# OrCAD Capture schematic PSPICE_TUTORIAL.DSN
size A
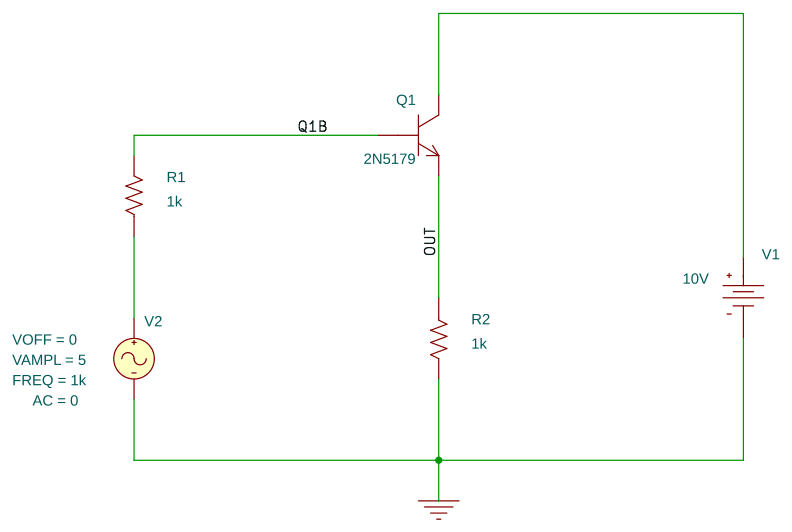
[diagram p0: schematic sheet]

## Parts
Q1  2N5179  [TO72]
R1  1k  [AXRC05]
R2  1k  [AXRC05]
V1  VDC
V2  VSIN

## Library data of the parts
Q1 = 2N5179
R1 R2 = R
V1 = VDC: DC: 10V
V2 = VSIN: AC: 0; AppProp: Sine$Voltage$0$-1; DC: 0; FREQ: 1k; VAMPL: 5; VOFF: 0

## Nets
0: R2.2 V1.1(-) V2.2(-)
OUT: Q1.1(E) R2.1
Q1B: Q1.2(B) R1.2
N00221: Q1.3(C) V1.0(+)
N00252: R1.1 V2.1(+)
